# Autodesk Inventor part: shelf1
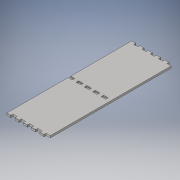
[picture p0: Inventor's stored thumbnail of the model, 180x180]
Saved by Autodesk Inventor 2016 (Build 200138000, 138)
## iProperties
Created: 2017-03
Part Number: shelf1
Material: Generic
Document SubType Name: Modeling
Designer: Corey
Density: 1 g/cm^3
Appearance: Default
Author: Corey
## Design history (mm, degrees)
sketch "Sketch1"
  geometry: L1 (0, 0)-(368.3, 0); L2 (368.3, 0)-(368.3, -1117.6); L3 (368.3, -1117.6)-(0, -1117.6); L4 (0, -1117.6)-(0, 0)
  constraints: 8 end point, 2 parallel, 1 horizontal, 1 perpendicular
  dimensions: "d0" = 368.3 distance of L2.end L3.end (= panel); "d1" = 1117.6 distance of L1.end L2.end (= width)
extrude "body" new body sketch "Sketch1" distance "d2" = 18.034 (= thick); taper "d3" = 0 deg
sketch "Sketch2"
  geometry: L1 (-368.3, 0)-(0, 0) reference; L2 (0, 0)-(-36.83, 0); L3 (-36.83, 0)-(-36.83, 21.209); L4 (-36.83, 21.209)-(0, 21.209); L5 (0, 21.209)-(0, 0); L6 (0, 0)-(0, 1117.6) reference; L7 (0, 558.8)-(-368.3, 558.8); L8 (-368.3, 1117.6)-(-368.3, 0) reference; L9 (0, 1117.6)-(-36.83, 1117.6); L10 (-36.83, 1117.6)-(-36.83, 1096.391); L11 (-36.83, 1096.391)-(0, 1096.391); L12 (0, 1096.391)-(0, 1117.6)
  constraints: 18 end point, 3 symmetric about line, 2 midpoint, 2 parallel, 1 horizontal, 1 perpendicular
  dimensions: "d4" = 36.83 distance of L3.end L4.end (= 0.1 x panel); "d5" = 21.209 distance of L2.end L3.end (= thick + 0.5 x bit)
extrude "sidetab" cut sketch "Sketch2" stored distance "d6" = 18.034 (= thick); taper "d7" = 0 deg
pattern_linear "sidetabP" dims "d10" = 73.66 (= 0.2 x panel)
chamfer "type2pressfit" distance "d11" = 2.25425 (= 0.125 x thick); stored, may be unused: second distance "d12" = 3.175, angle "d13" = 45 deg
sketch "Sketch3"
  geometry: L1 (-331.47, 549.783)-(-368.3, 549.783); L2 (-368.3, 549.783)-(-368.3, 567.817); L3 (-368.3, 567.817)-(-331.47, 567.817); L4 (-331.47, 567.817)-(-331.47, 549.783); L5 (-331.47, 549.783)-(-368.3, 567.817); L6 (-368.3, 549.783)-(-331.47, 567.817); L7 (0, 21.209)-(0, 1096.391) reference; L8 (-71.406, 0)-(-39.084, 0) reference; L9 (-368.3, 1115.346)-(-368.3, 2.254) reference; 2 further points
  constraints: 12 end point, 2 midpoint, 2 parallel, 1 collinear, 1 horizontal, 1 perpendicular
  dimensions: "d14" = 36.83 distance of L2.end L3.end (= 0.1 x panel); "d15" = 18.034 distance of L1.end L2.end (= thick); "d16" = 558.8 distance from line of L8 point (-349.885, 558.8) (= 0.5 x width)
extrude "centertab" cut sketch "Sketch3" distance "d17" = 9.017 (= 0.5 x thick); taper "d18" = 0 deg
pattern_linear "centertabP" dims "d21" = 73.66 (= 0.2 x panel)
chamfer "type2pressfit2" distance "d22" = 2.25425 (= 0.125 x thick); stored, may be unused: second distance "d23" = 3.175, angle "d24" = 45 deg
body "Solid1"
other parameters: "height" = 1917.7 [user parameter], "width" = 1117.6 [user parameter; used in 2 equation terms], "depth" = 425.45 [user parameter], "thick" = 18.034 [user parameter; used in 7 equation terms], "bit" = 6.35 [user parameter; used in 1 equation term], "top" = 152.4 [user parameter], "panel" = 368.3 [user parameter; used in 5 equation terms], "sweater" = 330.2 [user parameter], "shoe" = 152.4 [user parameter], "osb" = 19.05 [user parameter]
